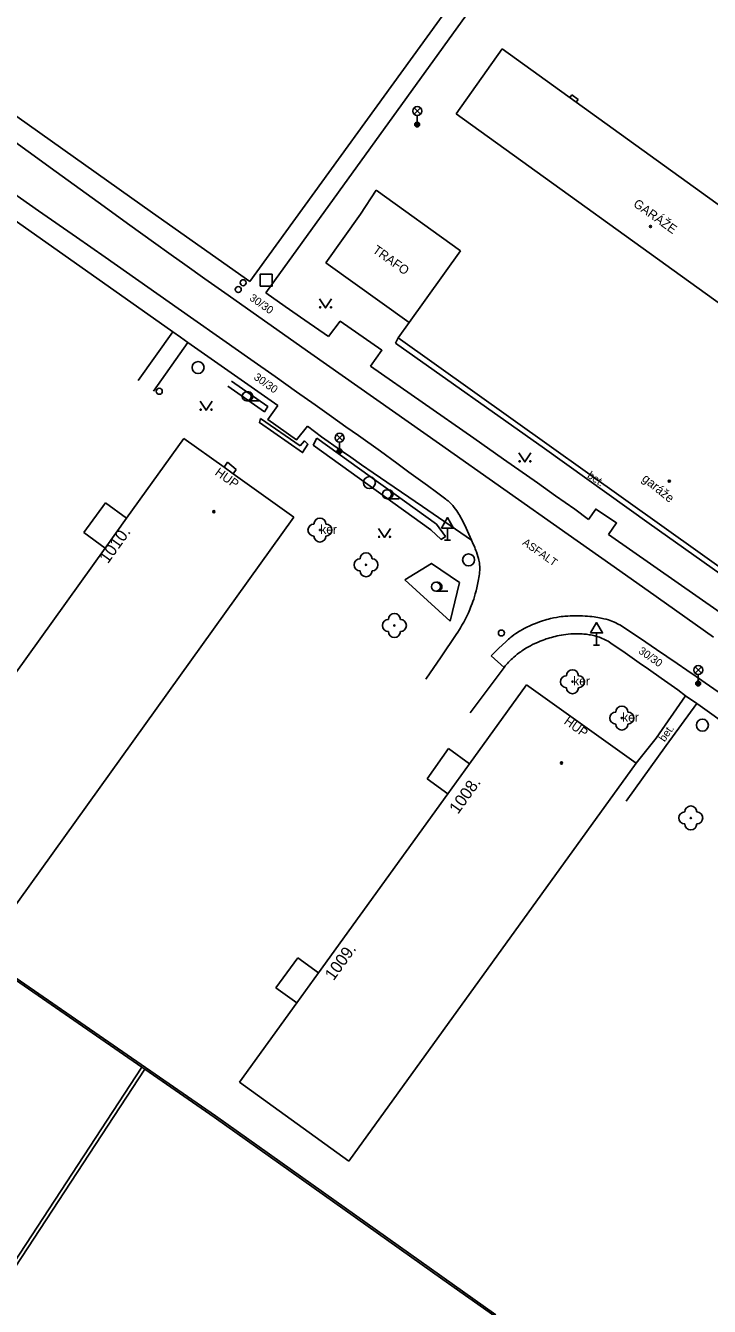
# Model space of a CAD drawing. Extents: x -539515 to -538098, y -1182060 to -1180157.
# Drawn here: x -538497 to -538439.9, y -1181228.2 to -1181121.5 of the extents above; entities that cross this region are included whole.
import ezdxf

# ---------------------------------------------------------------- set-up
doc = ezdxf.new("R2010")
doc.units = 0
for name, color, linetype in [('Vrstva 1', 7, 'Continuous'), ('Vrstva 13', 7, 'Continuous'), ('Vrstva 21', 7, 'Continuous'), ('Vrstva 22', 7, 'Continuous'), ('Vrstva 24', 7, 'Continuous'), ('Vrstva 26', 7, 'Continuous'), ('Vrstva 27', 7, 'Continuous'), ('Vrstva 28', 7, 'Continuous'), ('Vrstva 33', 7, 'Continuous'), ('Vrstva 34', 7, 'Continuous'), ('Vrstva 36', 7, 'Continuous'), ('Vrstva 39', 7, 'Continuous'), ('Vrstva 40', 7, 'Continuous'), ('Vrstva 41', 7, 'Continuous'), ('Vrstva 42', 7, 'Continuous'), ('Vrstva 47', 7, 'Continuous'), ('Vrstva 68', 7, 'Continuous'), ('Vrstva 88', 7, 'Continuous')]:
    doc.layers.add(name, color=color, linetype=linetype)

msp = doc.modelspace()

# ---------------------------------------------------------------- linework, layer by layer
at = {"layer": 'Vrstva 1'}
for p, q in [((-538461.07, -1181128.8), (-538457.22, -1181123.39)), ((-538427.17, -1181145.05), (-538457.22, -1181123.39)), ((-538431.02, -1181150.46), (-538461.07, -1181128.8)), ((-538469.029, -1181137.175), (-538467.74, -1181135.17)), ((-538467.74, -1181135.17), (-538460.69, -1181140.24)), ((-538469.029, -1181137.175), (-538471.94, -1181141.24)), ((-538471.94, -1181141.24), (-538464.989, -1181146.218)), ((-538421.05, -1181179.47), (-538465.89, -1181147.48)), ((-538498.513, -1181195.761), (-538474.61, -1181162.45)), ((-538446.05, -1181182.96), (-538455.18, -1181176.41)), ((-538470.02, -1181216.13), (-538446.05, -1181182.96)), ((-538479.127, -1181209.548), (-538470.02, -1181216.13))]:
    msp.add_line(p, q, dxfattribs=at)
for points in [[(-538460.69, -1181140.24), (-538464.989, -1181146.218)], [(-538464.989, -1181146.218), (-538465.89, -1181147.48)], [(-538488.551, -1181162.519), (-538483.78, -1181155.87)], [(-538483.78, -1181155.87), (-538480.421, -1181158.28)], [(-538480.421, -1181158.28), (-538479.657, -1181158.828)], [(-538479.657, -1181158.828), (-538474.61, -1181162.45)], [(-538490.341, -1181165.013), (-538488.551, -1181162.519)], [(-538507.683, -1181189.181), (-538490.341, -1181165.013)], [(-538459.938, -1181182.994), (-538455.18, -1181176.41)], [(-538461.746, -1181185.496), (-538459.938, -1181182.994)], [(-538472.542, -1181200.436), (-538461.746, -1181185.496)], [(-538474.35, -1181202.938), (-538472.542, -1181200.436)], [(-538479.127, -1181209.548), (-538474.35, -1181202.938)]]:
    msp.add_lwpolyline(points, dxfattribs=at)
at = {"layer": 'Vrstva 13'}
for p, q in [((-538460.81, -1181118.69), (-538478.273, -1181142.788)), ((-538458.65, -1181118.41), (-538476.94, -1181143.73)), ((-538486.398, -1181137.048), (-538498.582, -1181128.431)), ((-538478.273, -1181142.788), (-538486.398, -1181137.048)), ((-538484.69, -1181146.97), (-538498.11, -1181137.495)), ((-538475.317, -1181144.873), (-538476.94, -1181143.73)), ((-538487.574, -1181151.055), (-538484.69, -1181146.97)), ((-538466.11, -1181147.92), (-538465.89, -1181147.48)), ((-538486.315, -1181151.944), (-538483.43, -1181147.86)), ((-538475.94, -1181153.12), (-538483.43, -1181147.86)), ((-538453.69, -1181156.71), (-538466.11, -1181147.92)), ((-538459.584, -1181155.864), (-538468.2, -1181149.85)), ((-538457.105, -1181157.598), (-538459.584, -1181155.864)), ((-538444.95, -1181162.96), (-538453.69, -1181156.71)), ((-538492.119, -1181163.713), (-538490.307, -1181161.235)), ((-538488.551, -1181162.519), (-538490.307, -1181161.235)), ((-538490.341, -1181165.013), (-538492.119, -1181163.713)), ((-538434.91, -1181170.11), (-538444.95, -1181162.96)), ((-538457.06, -1181174.97), (-538458.15, -1181174.01)), ((-538440.99, -1181177.97), (-538443.53, -1181181.49)), ((-538461.7, -1181181.72), (-538463.47, -1181184.25)), ((-538459.938, -1181182.994), (-538461.7, -1181181.72)), ((-538443.53, -1181181.49), (-538446.868, -1181186.116)), ((-538461.746, -1181185.496), (-538463.47, -1181184.25)), ((-538500.728, -1181198.848), (-538481.148, -1181212.344)), ((-538474.28, -1181199.18), (-538476.09, -1181201.68)), ((-538472.542, -1181200.436), (-538474.28, -1181199.18)), ((-538474.35, -1181202.938), (-538476.09, -1181201.68)), ((-538503.23, -1181233.178), (-538487.038, -1181208.466)), ((-538457.74, -1181228.946), (-538481.148, -1181212.344))]:
    msp.add_line(p, q, dxfattribs=at)
for points in [[(-538471.71, -1181147.37), (-538473.692, -1181146.015), (-538475.317, -1181144.873)], [(-538471.71, -1181147.37), (-538470.73, -1181146.1), (-538467.26, -1181148.52), (-538468.2, -1181149.85)], [(-538483.43, -1181147.86), (-538484.06, -1181147.415), (-538484.69, -1181146.97)], [(-538475.94, -1181153.12), (-538476.77, -1181154.28), (-538474.38, -1181156), (-538473.45, -1181154.86)], [(-538467.97, -1181158.74), (-538468.944, -1181158.071), (-538469.855, -1181157.441), (-538470.708, -1181156.849), (-538472.305, -1181155.734), (-538473.45, -1181154.86)], [(-538451.16, -1181161.78), (-538452.767, -1181160.645), (-538454.275, -1181159.584), (-538457.105, -1181157.598)], [(-538459.78, -1181164.35), (-538463.875, -1181161.545), (-538467.97, -1181158.74)], [(-538450.03, -1181162.63), (-538451.16, -1181161.78)], [(-538450.03, -1181162.63), (-538449.41, -1181161.77), (-538447.68, -1181162.92), (-538448.34, -1181163.88)], [(-538435.255, -1181173.03), (-538448.34, -1181163.88)], [(-538445.792, -1181174.573), (-538446.97, -1181173.753), (-538448.15, -1181172.94), (-538448.269, -1181172.862), (-538448.388, -1181172.789), (-538448.509, -1181172.722), (-538448.63, -1181172.659), (-538448.751, -1181172.602), (-538448.873, -1181172.549), (-538448.995, -1181172.5), (-538449.117, -1181172.455), (-538449.238, -1181172.414), (-538449.36, -1181172.377), (-538449.481, -1181172.344), (-538449.601, -1181172.313), (-538449.721, -1181172.286), (-538449.841, -1181172.262), (-538449.959, -1181172.241), (-538450.077, -1181172.223), (-538450.193, -1181172.207), (-538450.309, -1181172.194), (-538450.423, -1181172.183), (-538450.537, -1181172.174), (-538450.649, -1181172.168), (-538450.872, -1181172.16), (-538451.09, -1181172.16), (-538451.302, -1181172.167), (-538451.508, -1181172.179), (-538451.709, -1181172.197), (-538451.904, -1181172.219), (-538452.093, -1181172.245), (-538452.277, -1181172.274), (-538452.454, -1181172.307), (-538452.626, -1181172.342), (-538452.792, -1181172.38), (-538452.952, -1181172.42), (-538453.107, -1181172.461), (-538453.256, -1181172.504), (-538453.4, -1181172.548), (-538453.539, -1181172.594), (-538453.672, -1181172.639), (-538453.801, -1181172.686), (-538454.048, -1181172.781), (-538454.277, -1181172.877), (-538454.487, -1181172.973), (-538454.682, -1181173.067), (-538454.862, -1181173.16)], [(-538454.862, -1181173.16), (-538455.027, -1181173.251), (-538455.18, -1181173.338), (-538455.32, -1181173.423), (-538455.45, -1181173.505), (-538455.569, -1181173.584), (-538455.679, -1181173.659), (-538455.78, -1181173.732), (-538455.965, -1181173.871), (-538456.122, -1181173.996)], [(-538456.122, -1181173.996), (-538456.255, -1181174.109), (-538456.368, -1181174.21), (-538456.464, -1181174.3), (-538456.546, -1181174.38), (-538456.685, -1181174.523), (-538456.784, -1181174.632), (-538456.857, -1181174.715), (-538456.961, -1181174.841), (-538457.06, -1181174.97), (-538458.47, -1181176.864), (-538459.881, -1181178.758)], [(-538442.571, -1181176.843), (-538443.963, -1181175.857), (-538445.008, -1181175.122), (-538445.792, -1181174.573)], [(-538441.92, -1181177.33), (-538444.39, -1181180.86), (-538446.05, -1181182.96)], [(-538441.92, -1181177.33), (-538442.571, -1181176.843)], [(-538440.99, -1181177.97), (-538441.92, -1181177.33)], [(-538434.951, -1181182.295), (-538438.247, -1181179.933), (-538440.717, -1181178.164), (-538440.99, -1181177.97)]]:
    msp.add_lwpolyline(points, dxfattribs=at)
at = {"layer": 'Vrstva 21'}
for p, q in [((-538474.06, -1181156.487), (-538477.38, -1181154.22)), ((-538472.69, -1181155.86), (-538472.99, -1181156.43)), ((-538462.7, -1181163.03), (-538472.69, -1181155.86)), ((-538472.99, -1181156.43), (-538463.17, -1181163.49)), ((-538465.35, -1181167.67), (-538461.56, -1181171.11)), ((-538461.56, -1181171.11), (-538460.77, -1181167.89))]:
    msp.add_line(p, q, dxfattribs=at)
for points in [[(-538479.81, -1181151.09), (-538476.78, -1181153.22), (-538477.05, -1181153.65), (-538480.102, -1181151.505)], [(-538477.38, -1181154.22), (-538477.47, -1181154.55), (-538473.87, -1181157.05), (-538473.42, -1181156.36), (-538473.71, -1181156.08), (-538474.06, -1181156.487)], [(-538463.17, -1181163.49), (-538462.31, -1181164.29), (-538461.96, -1181164.04), (-538462.7, -1181163.03)], [(-538460.77, -1181167.89), (-538463.13, -1181166.29), (-538465.35, -1181167.67)]]:
    msp.add_lwpolyline(points, dxfattribs=at)
at = {"layer": 'Vrstva 22'}
for centre in [(-538472.42, -1181163.51), (-538468.58, -1181166.41), (-538466.21, -1181171.47), (-538451.36, -1181176.16), (-538447.24, -1181179.19), (-538441.49, -1181187.52)]:
    msp.add_circle(centre, 0.05, dxfattribs=at)
for centre, start, end in [((-538472.42, -1181163.01), 0, 180), ((-538472.92, -1181163.51), 90, 270), ((-538471.92, -1181163.51), 270, 90), ((-538472.42, -1181164.01), 180, 0), ((-538469.08, -1181166.41), 90, 270), ((-538468.58, -1181165.91), 0, 180), ((-538468.08, -1181166.41), 270, 90), ((-538468.58, -1181166.91), 180, 0), ((-538466.71, -1181171.47), 90, 270), ((-538466.21, -1181170.97), 0, 180), ((-538465.71, -1181171.47), 270, 90), ((-538466.21, -1181171.97), 180, 0), ((-538451.36, -1181175.66), 0, 180), ((-538451.86, -1181176.16), 90, 270), ((-538450.86, -1181176.16), 270, 90), ((-538451.36, -1181176.66), 180, 0), ((-538447.74, -1181179.19), 90, 270), ((-538447.24, -1181178.69), 0, 180), ((-538446.74, -1181179.19), 270, 90), ((-538447.24, -1181179.69), 180, 0), ((-538441.99, -1181187.52), 90, 270), ((-538441.49, -1181187.02), 0, 180), ((-538440.99, -1181187.52), 270, 90), ((-538441.49, -1181188.02), 180, 0)]:
    msp.add_arc(centre, 0.5, start, end, dxfattribs=at)
at = {"layer": 'Vrstva 24'}
for p, q in [((-538451.4, -1181127.21), (-538451.577, -1181127.451)), ((-538451.047, -1181127.841), (-538451.577, -1181127.451)), ((-538450.87, -1181127.6), (-538451.4, -1181127.21)), ((-538450.87, -1181127.6), (-538451.047, -1181127.841)), ((-538480.421, -1181158.28), (-538480.12, -1181157.86)), ((-538480.12, -1181157.86), (-538479.4, -1181158.47)), ((-538479.657, -1181158.828), (-538479.4, -1181158.47))]:
    msp.add_line(p, q, dxfattribs=at)
at = {"layer": 'Vrstva 26'}
msp.add_lwpolyline([(-538477.41, -1181143.18), (-538476.41, -1181143.18), (-538476.41, -1181142.18), (-538477.41, -1181142.18)], close=True, dxfattribs=at)
at = {"layer": 'Vrstva 27'}
for centre in [(-538482.59, -1181149.96), (-538468.3, -1181159.56), (-538460.023, -1181166), (-538440.52, -1181179.78)]:
    msp.add_circle(centre, 0.5, dxfattribs=at)
at = {"layer": 'Vrstva 28'}
for centre in [(-538479.233, -1181143.456), (-538478.83, -1181142.885), (-538485.824, -1181151.942), (-538457.285, -1181172.096)]:
    msp.add_circle(centre, 0.25, dxfattribs=at)
at = {"layer": 'Vrstva 33'}
for p, q in [((-538464.575, -1181128.84), (-538464.045, -1181128.31)), ((-538464.575, -1181128.31), (-538464.045, -1181128.84)), ((-538464.31, -1181128.95), (-538464.31, -1181129.7)), ((-538471.054, -1181156.081), (-538470.526, -1181155.551)), ((-538471.054, -1181155.551), (-538470.526, -1181156.081)), ((-538470.79, -1181156.19), (-538470.79, -1181156.94)), ((-538441.135, -1181175.45), (-538440.605, -1181174.92)), ((-538441.135, -1181174.92), (-538440.605, -1181175.45)), ((-538440.87, -1181175.56), (-538440.87, -1181176.31))]:
    msp.add_line(p, q, dxfattribs=at)
for centre, radius in [((-538464.31, -1181128.575), 0.375), ((-538464.31, -1181129.7), 0.2), ((-538464.31, -1181129.7), 0.145), ((-538464.31, -1181129.7), 0.0876), ((-538470.79, -1181155.816), 0.375), ((-538470.79, -1181156.941), 0.2), ((-538470.79, -1181156.941), 0.145), ((-538470.79, -1181156.941), 0.0876), ((-538440.87, -1181175.185), 0.375), ((-538440.87, -1181176.31), 0.2), ((-538440.87, -1181176.31), 0.145), ((-538440.87, -1181176.31), 0.0876)]:
    msp.add_circle(centre, radius, dxfattribs=at)
at = {"layer": 'Vrstva 34'}
for p, q in [((-538461.78, -1181163.344), (-538461.78, -1181164.36)), ((-538462.03, -1181164.36), (-538461.53, -1181164.36)), ((-538449.35, -1181172.094), (-538449.35, -1181173.11)), ((-538449.6, -1181173.11), (-538449.1, -1181173.11))]:
    msp.add_line(p, q, dxfattribs=at)
for points in [[(-538462.28, -1181163.344), (-538461.28, -1181163.344), (-538461.78, -1181162.476)], [(-538449.85, -1181172.094), (-538448.85, -1181172.094), (-538449.35, -1181171.226)]]:
    msp.add_lwpolyline(points, close=True, dxfattribs=at)
at = {"layer": 'Vrstva 36'}
for p, q in [((-538478.524, -1181152.744), (-538477.524, -1181152.744)), ((-538466.826, -1181160.895), (-538465.826, -1181160.895)), ((-538462.752, -1181168.613), (-538461.752, -1181168.613))]:
    msp.add_line(p, q, dxfattribs=at)
for points in [[(-538472.451, -1181144.241), (-538471.951, -1181144.991), (-538471.451, -1181144.241)], [(-538482.418, -1181152.778), (-538481.918, -1181153.528), (-538481.418, -1181152.778)], [(-538455.819, -1181157.077), (-538455.319, -1181157.827), (-538454.819, -1181157.077)], [(-538467.527, -1181163.374), (-538467.027, -1181164.124), (-538466.527, -1181163.374)]]:
    msp.add_lwpolyline(points, dxfattribs=at)
for centre, radius in [((-538472.401, -1181144.941), 0.05), ((-538471.502, -1181144.941), 0.05), ((-538478.524, -1181152.369), 0.375), ((-538482.368, -1181153.478), 0.05), ((-538481.469, -1181153.478), 0.05), ((-538455.769, -1181157.777), 0.05), ((-538454.87, -1181157.777), 0.05), ((-538466.826, -1181160.52), 0.375), ((-538467.477, -1181164.074), 0.05), ((-538466.578, -1181164.074), 0.05), ((-538462.752, -1181168.238), 0.375)]:
    msp.add_circle(centre, radius, dxfattribs=at)
for centre in [(-538478.399, -1181152.369), (-538466.701, -1181160.52), (-538462.627, -1181168.238)]:
    msp.add_arc(centre, 0.375, 260.40593, 99.59406, dxfattribs=at)
at = {"layer": 'Vrstva 39'}
for centre, radius in [((-538444.848, -1181138.199), 0.09), ((-538444.848, -1181138.199), 0.0398), ((-538443.284, -1181159.431), 0.09), ((-538443.284, -1181159.431), 0.0398), ((-538481.274, -1181161.984), 0.09), ((-538481.274, -1181161.984), 0.0398), ((-538452.272, -1181182.941), 0.09), ((-538452.272, -1181182.941), 0.0398)]:
    msp.add_circle(centre, radius, dxfattribs=at)
at = {"layer": 'Vrstva 68'}
for p, q in [((-538503.481, -1181233.014), (-538487.285, -1181208.295)), ((-538462.166, -1181225.99), (-538481.235, -1181212.465)), ((-538457.821, -1181229.072), (-538462.166, -1181225.99))]:
    msp.add_line(p, q, dxfattribs=at)
for points in [[(-538487.285, -1181208.295), (-538500.897, -1181198.913)], [(-538487.038, -1181208.466), (-538487.285, -1181208.295)], [(-538481.235, -1181212.465), (-538487.038, -1181208.466)]]:
    msp.add_lwpolyline(points, dxfattribs=at)
at = {"layer": 'Vrstva 88'}
for p, q in [((-538499.115, -1181130.247), (-538494.435, -1181133.635)), ((-538500.14, -1181133.94), (-538495.902, -1181136.885)), ((-538480.35, -1181143.74), (-538473.193, -1181148.779)), ((-538473.193, -1181148.779), (-538462.451, -1181156.33)), ((-538462.451, -1181156.33), (-538451.71, -1181163.88)), ((-538445.031, -1181168.587), (-538439.581, -1181172.439)), ((-538462.322, -1181174.082), (-538463.585, -1181175.933))]:
    msp.add_line(p, q, dxfattribs=at)
for points in [[(-538494.435, -1181133.635), (-538490.924, -1181136.176), (-538488.288, -1181138.078)], [(-538495.902, -1181136.885), (-538492.726, -1181139.097), (-538490.346, -1181140.758)], [(-538488.288, -1181138.078), (-538486.309, -1181139.501), (-538484.822, -1181140.565), (-538483.706, -1181141.362), (-538482.03, -1181142.553), (-538480.35, -1181143.74)], [(-538490.346, -1181140.758), (-538486.777, -1181143.256), (-538484.993, -1181144.507), (-538483.21, -1181145.76)], [(-538483.21, -1181145.76), (-538480.537, -1181147.638)], [(-538480.537, -1181147.638), (-538478.2, -1181149.279), (-538476.157, -1181150.715), (-538474.371, -1181151.973), (-538472.81, -1181153.076)], [(-538472.81, -1181153.076), (-538471.446, -1181154.043), (-538470.252, -1181154.892)], [(-538470.252, -1181154.892), (-538469.209, -1181155.637), (-538467.385, -1181156.947), (-538466.019, -1181157.934), (-538464.996, -1181158.678), (-538463.462, -1181159.8), (-538462.696, -1181160.364)], [(-538462.696, -1181160.364), (-538461.93, -1181160.93), (-538461.83, -1181161.007), (-538461.736, -1181161.085), (-538461.648, -1181161.162), (-538461.566, -1181161.24), (-538461.489, -1181161.317), (-538461.416, -1181161.394), (-538461.348, -1181161.47), (-538461.283, -1181161.545), (-538461.222, -1181161.619)], [(-538461.222, -1181161.619), (-538461.109, -1181161.767), (-538461.007, -1181161.91), (-538460.916, -1181162.047), (-538460.833, -1181162.178), (-538460.758, -1181162.304), (-538460.69, -1181162.424), (-538460.567, -1181162.653), (-538460.463, -1181162.857), (-538460.375, -1181163.039), (-538460.225, -1181163.362), (-538460.004, -1181163.855), (-538459.78, -1181164.35), (-538459.632, -1181164.677), (-538459.57, -1181164.821), (-538459.513, -1181164.957), (-538459.462, -1181165.084), (-538459.416, -1181165.204), (-538459.374, -1181165.316), (-538459.303, -1181165.526), (-538459.246, -1181165.711), (-538459.203, -1181165.872), (-538459.17, -1181166.013), (-538459.146, -1181166.136)], [(-538451.71, -1181163.88), (-538448.147, -1181166.389), (-538445.031, -1181168.587)], [(-538459.146, -1181166.136), (-538459.127, -1181166.244), (-538459.114, -1181166.338), (-538459.104, -1181166.42), (-538459.093, -1181166.563), (-538459.088, -1181166.67), (-538459.088, -1181166.751), (-538459.091, -1181166.871), (-538459.1, -1181166.99), (-538459.118, -1181167.157), (-538459.138, -1181167.319), (-538459.161, -1181167.477), (-538459.185, -1181167.63), (-538459.212, -1181167.78), (-538459.239, -1181167.924), (-538459.268, -1181168.065), (-538459.331, -1181168.337), (-538459.395, -1181168.593), (-538459.462, -1181168.832), (-538459.53, -1181169.057), (-538459.598, -1181169.267), (-538459.665, -1181169.463), (-538459.731, -1181169.646), (-538459.796, -1181169.817), (-538459.86, -1181169.976), (-538459.921, -1181170.125), (-538460.041, -1181170.403), (-538460.152, -1181170.643), (-538460.253, -1181170.85), (-538460.345, -1181171.03), (-538460.427, -1181171.186), (-538460.576, -1181171.456), (-538460.692, -1181171.654), (-538460.782, -1181171.801), (-538460.919, -1181172.018), (-538461.06, -1181172.23), (-538462.322, -1181174.082)], [(-538458.15, -1181174.01), (-538457.52, -1181173.4), (-538456.891, -1181172.791), (-538456.784, -1181172.69), (-538456.682, -1181172.6), (-538456.585, -1181172.517), (-538456.493, -1181172.442), (-538456.405, -1181172.374), (-538456.237, -1181172.25), (-538456.086, -1181172.146), (-538455.951, -1181172.058), (-538455.83, -1181171.984), (-538455.723, -1181171.92), (-538455.531, -1181171.811), (-538455.383, -1181171.732), (-538455.155, -1181171.615), (-538454.92, -1181171.5), (-538454.798, -1181171.443), (-538454.68, -1181171.39), (-538454.451, -1181171.293), (-538454.236, -1181171.209), (-538454.034, -1181171.137), (-538453.845, -1181171.074), (-538453.667, -1181171.019), (-538453.5, -1181170.972), (-538453.344, -1181170.931), (-538453.197, -1181170.895), (-538453.06, -1181170.864), (-538452.931, -1181170.837), (-538452.689, -1181170.792), (-538452.478, -1181170.758), (-538452.293, -1181170.733), (-538452.131, -1181170.714), (-538451.989, -1181170.7), (-538451.742, -1181170.68), (-538451.556, -1181170.67), (-538451.278, -1181170.661), (-538451, -1181170.66), (-538450.757, -1181170.664), (-538450.527, -1181170.672), (-538450.31, -1181170.682), (-538450.105, -1181170.696), (-538449.912, -1181170.712), (-538449.732, -1181170.73), (-538449.562, -1181170.751), (-538449.403, -1181170.773), (-538449.255, -1181170.797)], [(-538449.255, -1181170.797), (-538449.116, -1181170.822), (-538448.986, -1181170.848), (-538448.865, -1181170.874), (-538448.751, -1181170.901), (-538448.541, -1181170.956), (-538448.358, -1181171.011), (-538448.2, -1181171.064), (-538448.063, -1181171.114), (-538447.944, -1181171.161), (-538447.841, -1181171.204), (-538447.752, -1181171.245), (-538447.597, -1181171.319), (-538447.483, -1181171.379), (-538447.398, -1181171.427), (-538447.273, -1181171.501), (-538447.15, -1181171.58), (-538446.179, -1181172.229), (-538445.244, -1181172.858), (-538444.343, -1181173.468), (-538443.475, -1181174.058), (-538442.638, -1181174.631), (-538441.83, -1181175.185), (-538441.051, -1181175.723)], [(-538441.051, -1181175.723), (-538440.3, -1181176.243), (-538439.574, -1181176.748), (-538438.873, -1181177.237), (-538437.522, -1181178.184), (-538436.261, -1181179.073), (-538435.083, -1181179.906), (-538433.984, -1181180.687), (-538432.955, -1181181.42)]]:
    msp.add_lwpolyline(points, dxfattribs=at)

# ---------------------------------------------------------------- texts
at = {"layer": 'Vrstva 40'}
for s, rotation, p in [('30/30', 324.85327, (-538478.366, -1181144.291)), ('30/30', 324.63961, (-538478.001, -1181150.89)), ('bet.', 325.35674, (-538450.174, -1181159.091)), ('ASFALT', 324.89075, (-538455.587, -1181164.684)), ('30/30', 324.90151, (-538445.915, -1181173.726)), ('bet.', 54.96521, (-538443.677, -1181181.221))]:
    msp.add_text(s, height=0.65, rotation=rotation, dxfattribs=at).set_placement(p)
at = {"layer": 'Vrstva 41'}
for s, rotation, p in [('GARÁŽE', 324.49497, (-538446.346, -1181136.461)), ('TRAFO', 324.39143, (-538468.09, -1181140.307)), ('HUP', 324.33839, (-538481.245, -1181158.851)), ('garáže', 320.90644, (-538445.628, -1181159.34)), ('HUP', 324.34377, (-538452.129, -1181179.61))]:
    msp.add_text(s, height=0.75, rotation=rotation, dxfattribs=at).set_placement(p)
at = {"layer": 'Vrstva 42'}
for p in [(-538472.399, -1181163.831), (-538451.298, -1181176.473), (-538447.216, -1181179.495)]:
    msp.add_text('ker', height=0.75, dxfattribs=at).set_placement(p)
at = {"layer": 'Vrstva 47'}
for s, p in [('1010.', (-538490.113, -1181166.374)), ('1008.', (-538460.907, -1181187.258)), ('1009.', (-538471.291, -1181201.149))]:
    msp.add_text(s, height=1, rotation=54.33839, dxfattribs=at).set_placement(p)

doc.saveas('drawing.dxf')
